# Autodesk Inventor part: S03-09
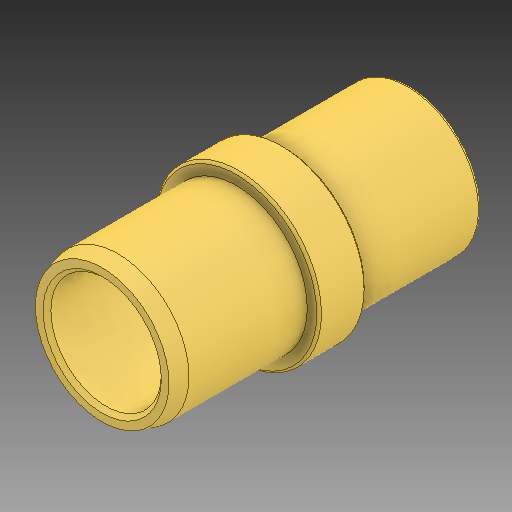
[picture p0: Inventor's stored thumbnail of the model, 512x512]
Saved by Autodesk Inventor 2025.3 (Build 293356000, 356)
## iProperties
Created: 2025-05
Part Number: S03-09
Material: Všeobecné
Document SubType Name: Modeling
Designer: Patrik
Density: 1 g/cm^3
Appearance: Výchozí
Mass: 4.42002 g
Surface Area: 42.7147 cm^2
Volume: 4.42002 cm^3
Description: Vodící pouzdro pro vyhazovací paket, mosaz
Stock Number: E 1120_14-17_22
User Status: 2.0598
Sending System: KiM GmbH
Major Version: 4.0
Minor Version: 0.0
Format Version: 0.0
Product Id: KiM GmbH
Material: 2.0598 200 HB
Hersteller: Meusburger
Bestellnummer: E 1120/14-17/22
Teilenummer: E 1120/14-17/22
Beschreibung: Führungsbuchse für Auswerferpaket, Messing _ Brass guide bush for ejector set
Author: Patrik
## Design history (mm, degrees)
feature "E 1120_14-17_22_1_1:1"
node "Těleso1"
